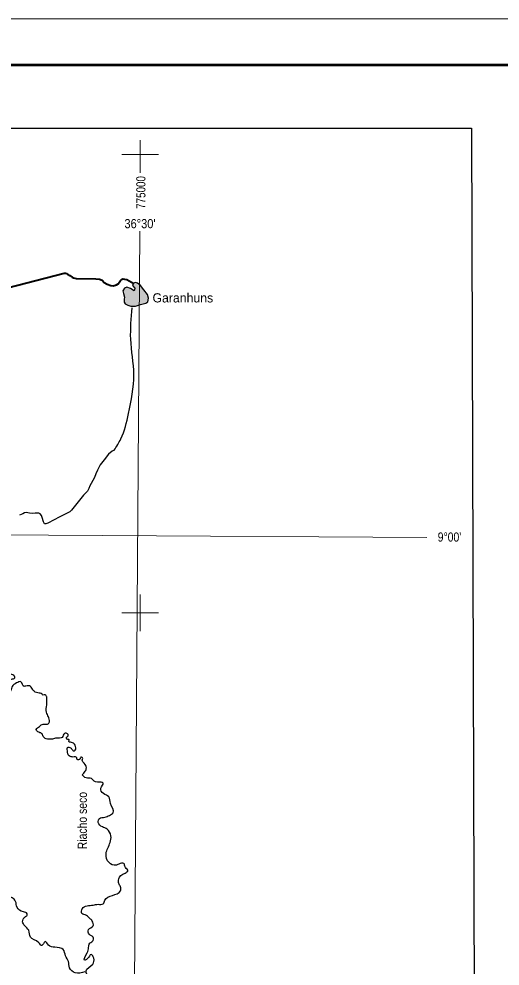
# Model space of a CAD drawing. Extents: x 553962 to 842807, y 8883888 to 9032388.
# Drawn here: x 768390 to 794627, y 8980740 to 9032388 of the extents above; entities that cross this region are included whole.
import ezdxf
from ezdxf.enums import TextEntityAlignment as Align

# ---------------------------------------------------------------- set-up
doc = ezdxf.new("R2010")
doc.units = 0
doc.header["$LTSCALE"] = 200
for name, color, linetype, lineweight in [('1', 7, 'Continuous', 13), ('12', 7, 'Continuous', 25), ('2', 7, 'Continuous', 13), ('21', 7, 'Continuous', 25), ('24', 7, 'Continuous', 25), ('3', 7, 'Continuous', 13)]:
    doc.layers.add(name, color=color, linetype=linetype, lineweight=lineweight)
for name, color, linetype in [('41', 7, 'Continuous'), ('46', 7, 'Continuous'), ('47', 7, 'Continuous'), ('49', 7, 'Continuous')]:
    doc.layers.add(name, color=color, linetype=linetype)

msp = doc.modelspace()

# ---------------------------------------------------------------- hatches: boundary and pattern name
at = {"layer": '21'}
msp.add_hatch(color=256, dxfattribs=at).paths.add_polyline_path([(774642.6, 9017970.5), (774590, 9017853.5), (774707, 9017703.1), (774699.9, 9017607.5), (774666.4, 9017564.6), (774465.8, 9017695.9), (774272.4, 9017755.6), (774141.1, 9017703.1), (774059.9, 9017559.8), (774088.6, 9017407), (774150.6, 9017220.7), (774131.5, 9017098.9), (774119.6, 9016950.8), (774174.5, 9016850.6), (774322.6, 9016774.1), (774496.9, 9016721.6), (774740.5, 9016728.8), (775024.6, 9016812.3), (775308.8, 9016886.4), (775418.6, 9016962.8), (775461.6, 9017165.8), (775401.9, 9017366.4), (775199, 9017617.1), (775010.3, 9017846.3), (774859.9, 9017984.8), (774742.8, 9018020.7)])

# ---------------------------------------------------------------- linework, layer by layer
at = {"layer": '1'}
for points in [[(774987.1, 9020818), (774482.3, 8948876), (774053.6, 8890875.3)], [(565303.2, 9005146.6), (664889.8, 9004806.7), (719872.1, 9004543.9), (790635.8, 9004109)]]:
    msp.add_lwpolyline(points, dxfattribs=at)
at = {"layer": '12', "lineweight": 40}
msp.add_lwpolyline([(756511.8, 9014822.1), (770853.3, 9018520.5), (770924.2, 9018521.6), (770985.1, 9018512.5), (771046.6, 9018462.9), (771159, 9018394), (771296.8, 9018315.3), (771363.3, 9018270.9), (771439.6, 9018246.8), (771515.7, 9018237.9), (772584.4, 9018214.5), (772792.2, 9018202.7), (772924.7, 9018144.2), (773037.8, 9018024.7), (773196.2, 9017926.1), (773399.7, 9017858.6), (773526.7, 9017830.3), (773718.2, 9017894), (773793.5, 9017940.7), (773853.2, 9018012.4), (773922.3, 9018129.7), (773982.4, 9018176.2), (774057.9, 9018207.7), (774154.2, 9018199.1), (774276, 9018180.9), (774647, 9017969.3)], dxfattribs=at)
at = {"layer": '12'}
msp.add_lwpolyline([(773619.5, 9008873.2), (773587.2, 9008870.6), (773476.6, 9008818.3), (773271.3, 9008663.4), (773032.9, 9008346.2), (772824.1, 9008080.1), (772676.6, 9007784.6), (772578.4, 9007575.8), (772510.4, 9007377.7), (772338, 9007051.5), (772258.8, 9006923.8), (772200.1, 9006786.5), (772121.2, 9006638.6), (772006.6, 9006510.5), (771906.7, 9006417.9), (771255.5, 9005598.9), (771165.5, 9005516.6), (770688.2, 9005266.4), (770582.6, 9005214.1), (770316.2, 9005078.5), (769969.7, 9004886), (769853.6, 9004863.9), (769792.8, 9004862.9), (769725.5, 9004968), (769651, 9005209.4), (769624.2, 9005310), (769552.1, 9005394.8), (769470.5, 9005439), (769278.1, 9005435.9), (769146.7, 9005418.7), (768969.3, 9005431), (768781.4, 9005468.4), (768690.5, 9005456.9), (768600, 9005409.9), (768419.6, 9005320.2)], dxfattribs=at)
msp.add_spline([(773587.2, 9008870.6), (773945.5, 9009485.9), (774363.7, 9010866.4), (774656.4, 9013000.1), (774489.1, 9014924.5), (774572.8, 9016639.8)], degree=3, dxfattribs=at)
at = {"layer": '2'}
for p, q in [((775000, 9024000), (775000, 9025783.6)), ((774000, 9025000), (776000, 9025000)), ((775000, 8999000), (775000, 9001000)), ((774000, 9000000), (776000, 9000000))]:
    msp.add_line(p, q, dxfattribs=at)
at = {"layer": '21'}
msp.add_lwpolyline([(774642.6, 9017970.5), (774590, 9017853.5), (774707, 9017703.1), (774699.9, 9017607.5), (774666.4, 9017564.6), (774465.8, 9017695.9), (774272.4, 9017755.6), (774141.1, 9017703.1), (774059.9, 9017559.8), (774088.6, 9017407), (774150.6, 9017220.7), (774131.5, 9017098.9), (774119.6, 9016950.8), (774174.5, 9016850.6), (774322.6, 9016774.1), (774496.9, 9016721.6), (774740.5, 9016728.8), (775024.6, 9016812.3), (775308.8, 9016886.4), (775418.6, 9016962.8), (775461.6, 9017165.8), (775401.9, 9017366.4), (775199, 9017617.1), (775010.3, 9017846.3), (774859.9, 9017984.8), (774742.8, 9018020.7)], close=True, dxfattribs=at)
at = {"layer": '24'}
for points in [[(771454.5, 8992786.6), (771363.4, 8992894.2), (771259, 8992936.7), (771154.7, 8992956), (771112.2, 8992994.7), (771127.6, 8993052.7), (771104.5, 8993091.4), (771004, 8993114.6), (770984.7, 8993219), (771054.2, 8993269.2), (771081.3, 8993323.4), (770961.5, 8993435.5), (770876.5, 8993423.9), (770745.1, 8993211.2), (770443.7, 8993172.6), (770227.3, 8993114.6), (770072.7, 8993110.7), (769817.6, 8993157.1), (769694, 8993307.9), (769655.3, 8993400.7), (769477.6, 8993485.8), (769338.5, 8993640.5), (769404.2, 8993733.3), (769520.1, 8993806.7), (769601.2, 8993895.7), (769833.1, 8993922.7), (770026.3, 8993980.7), (770053.4, 8994139.3), (770026.3, 8994270.7), (769918.1, 8994514.3), (769875.6, 8994672.9), (769914.3, 8995094.4), (769910.4, 8995237.4), (769910.4, 8995419.2), (769879.5, 8995477.2), (769829.2, 8995523.6), (769713.3, 8995519.7), (769655.3, 8995566.1), (769425.4, 8995635.7), (769162.7, 8995774.9), (769023.6, 8995991.4), (768760.8, 8996006.9), (768683.5, 8995991.4), (768498, 8996238.9), (768266.2, 8996177), (768018.8, 8995991.4), (767941.5, 8995759.4), (767740.6, 8995620.2), (767632.4, 8995697.6), (767323.3, 8995728.5), (767431.5, 8995945), (767663.3, 8996022.4), (767771.5, 8996238.9), (767987.9, 8996393.6), (768157.9, 8996455.5), (768142.5, 8996548.2), (767941.5, 8996656.5), (767833.3, 8996702.9), (767323.3, 8996409.1), (767014.1, 8996625.6), (766998.7, 8996981.3), (767091.4, 8997151.5), (766735.9, 8997136), (766148.5, 8997120.5), (766086.7, 8997429.9), (766210.3, 8997770.2), (766117.6, 8997924.8), (765932.1, 8997832), (765715.7, 8997940.3), (765823.9, 8998218.7), (765793, 8998435.2), (765793, 8998729.1), (765576.6, 8998837.4), (765375.7, 8998775.5), (765252, 8998992.1), (765329.3, 8999409.7), (765004.7, 8999517.9), (764772.8, 8999332.3), (764633.7, 8998976.6), (764278.2, 8998667.2), (764061.8, 8998760), (764200.9, 8999440.6), (764479.1, 8999657.1), (764602.8, 8999873.7), (764231.8, 9000059.3), (763690.8, 9000616.1), (763752.6, 9000832.6), (763969, 9001018.2), (764200.9, 9001126.5), (764355.5, 9001528.7), (764711, 9001606)], [(771983.6, 8980431.6), (771458.1, 8980369.7), (771148.9, 8980648.1), (771087.1, 8980988.4), (770932.5, 8981297.7), (770808.9, 8981638), (770345.2, 8981761.8), (770005.1, 8981885.5), (769819.6, 8982071.1), (769634.1, 8981854.6), (769479.5, 8982009.2), (769015.8, 8982318.6), (768923.1, 8982689.8), (768706.7, 8982937.2), (768593.5, 8983157.4), (768713.2, 8983415.3), (768842, 8983516.6), (768842, 8983590.2), (768630.3, 8983700.8), (768289.8, 8983940.2), (768207, 8984262.5), (768022.9, 8984465.2), (767700.8, 8984557.2), (767590.3, 8984640.1), (767553.5, 8985036.1), (767599.5, 8985266.4), (767599.5, 8985422.9), (767461.5, 8985607.1), (767314.2, 8985634.8), (767268.2, 8985533.4), (767139.4, 8985496.6), (766918.5, 8985616.3), (766789.6, 8985818.9), (766559.5, 8985957.1), (766219, 8986297.8), (765850.9, 8986500.4), (765363.1, 8986924.1), (764801.7, 8987504.3), (764663.6, 8987624), (764378.3, 8988066), (764295.5, 8988259.4), (764221.8, 8988296.3), (764083.8, 8988204.2), (763982.5, 8988268.6), (763669.6, 8988664.7), (763586.8, 8988683.1), (763540.8, 8988848.8), (763605.2, 8988913.3), (763665, 8988922.5), (763720.2, 8989088.3), (763554.6, 8989254.1), (763480.9, 8989475.1), (763628.2, 8989677.7), (763977.9, 8989935.6), (764143.6, 8990101.3), (764125.2, 8990285.5), (763849.1, 8990377.6), (763793.9, 8990525), (763591.4, 8990617.1), (763480.9, 8990635.5), (763260.1, 8990525), (763094.4, 8990525), (762965.5, 8990635.5), (762818.3, 8990856.5), (762781.5, 8990930.2), (762652.6, 8990967), (762450.1, 8991169.6), (762082, 8991335.4), (761916.3, 8991464.3), (761750.7, 8991464.3), (761640.2, 8991261.7), (761456.2, 8991059.1), (761382.5, 8990967), (761290.5, 8990948.6), (761198.5, 8991059.1), (761143.2, 8991298.6), (760867.1, 8991464.3), (760738.3, 8991666.9), (760499, 8991795.9), (760351.7, 8992035.3), (760094, 8992495.8), (759854.7, 8992403.7), (759652.3, 8992256.3), (759394.6, 8992477.3), (758971.2, 8992643.1), (758731.9, 8992753.6), (758639.9, 8993048.3), (758566.2, 8993324.6), (758695.1, 8993508.8), (758916, 8993453.6), (758879.2, 8993619.3)], [(771844.7, 8991166.7), (772006.9, 8991369.5), (772067.7, 8991552), (771954.6, 8991796), (771846.4, 8991966.2), (771873.5, 8992066.7), (771842.5, 8992113.1), (771769.1, 8992132.4), (771715, 8992043.5), (771645.5, 8991985.5), (771564.3, 8992012.6), (771545, 8992101.5), (771351.8, 8992140.2), (771235.8, 8992151.8), (771050.3, 8992314.2), (771034.9, 8992480.4), (771023.3, 8992604.2), (771077.4, 8992677.6), (771162.4, 8992654.4), (771232, 8992615.8), (771332.5, 8992499.8), (771382.7, 8992476.6), (771456.1, 8992507.5), (771498.6, 8992646.7), (771452.2, 8992793.6)], [(774675.9, 8971457.7), (774621.3, 8971839.9), (774398.4, 8971961.6), (774175.5, 8972002.1), (774175.5, 8972387.4), (774317.3, 8972793), (774398.4, 8972955.3), (774297.1, 8973158.1), (773891.7, 8973300), (773810.7, 8973421.7), (773506.6, 8973847.6), (773222.9, 8973888.2), (773182.4, 8974151.8), (773222.9, 8974314), (773466.1, 8974334.3), (773648.5, 8974557.4), (773871.5, 8974618.2), (774094.4, 8974435.7), (774317.3, 8974598), (774540.3, 8974902.2), (774722.7, 8975105), (774580.8, 8975226.6), (774175.5, 8975186.1), (773749.8, 8975429.4), (773668.8, 8975936.4), (773385, 8976402.9), (773324.2, 8976930.1), (773486.4, 8977538.5), (773810.7, 8978248.3), (773810.7, 8978430.9), (773466.1, 8978430.9), (773182.4, 8978491.7), (772918.9, 8979100.1), (772817.6, 8979221.8), (772371.7, 8979465.1), (772189.3, 8980093.8), (772047.4, 8980479.1), (772412.2, 8980844.2), (772473, 8981168.7), (772331.2, 8981371.5), (772108.2, 8981128.1), (771966.3, 8981067.3), (772108.2, 8981452.6), (772189.3, 8981756.8), (772250.1, 8981979.9), (772392, 8982081.3), (772432.5, 8982324.6), (772229.8, 8982466.6), (772189.3, 8982730.2), (772432.5, 8982933), (772392, 8983196.7), (772250.1, 8983338.6), (772067.7, 8983500.8), (771824.5, 8983602.2), (771844.8, 8983865.9), (772432.5, 8984068.7), (772716.2, 8984109.2), (772979.7, 8984129.5), (773081, 8984332.3), (773486.4, 8984596), (773932.3, 8984839.3), (773932.3, 8985062.4), (773830.9, 8985244.9), (773830.9, 8985488.3), (774175.5, 8985812.8), (774337.6, 8985934.5), (774195.7, 8986117), (774114.7, 8986340.1), (773830.9, 8986299.5), (773668.8, 8986238.7), (773304, 8986380.6), (773141.8, 8986867.3), (773364.8, 8987475.7), (773405.3, 8987840.8), (773202.6, 8988205.8), (772939.2, 8988327.5), (772716.2, 8988570.8), (772777, 8988793.9), (773081, 8988854.8), (773324.2, 8988956.2), (773526.9, 8989098.1), (773385, 8989605.1), (773283.7, 8989970.2), (773000, 8990152.7), (772858.1, 8990436.6), (772979.7, 8990720.5), (772878.4, 8990761.1), (772493.3, 8990821.9), (772351.4, 8990963.9), (772047.4, 8991004.4), (771844.7, 8991166.7)]]:
    msp.add_spline(points, degree=3, dxfattribs=at)
at = {"layer": '3'}
msp.add_lwpolyline([(842807.3, 9032387.8), (842807.3, 8883887.8), (553961.7, 8883887.8), (553961.7, 9032387.8)], close=True, dxfattribs=at)
msp.add_lwpolyline([(842807.3, 9032387.8), (842807.3, 8883887.8), (553961.7, 8883887.8), (553961.7, 9032387.8)], close=True, dxfattribs=at)
at = {"layer": '3', "lineweight": 53}
msp.add_lwpolyline([(840307.3, 9029887.8), (840307.3, 8886387.8), (560211.7, 8886387.8), (560211.7, 9029887.8)], close=True, dxfattribs=at)
msp.add_lwpolyline([(840307.3, 9029887.8), (840307.3, 8886387.8), (560211.7, 8886387.8), (560211.7, 9029887.8)], close=True, dxfattribs=at)
at = {"layer": '3', "lineweight": 25}
msp.add_lwpolyline([(563033.9, 9026438.8), (793061.1, 9026438.8), (793495.6, 8889836.8), (563468.3, 8889836.8)], close=True, dxfattribs=at)
msp.add_lwpolyline([(563033.9, 9026438.8), (793061.1, 9026438.8), (793495.6, 8889836.8), (563468.3, 8889836.8)], close=True, dxfattribs=at)

# ---------------------------------------------------------------- texts
at = {"layer": '41'}
msp.add_text('Garanhuns', height=500, dxfattribs=at).set_placement((775675, 9016928.7))
at = {"layer": '46'}
for s, width, p in [("36°30'", 0.9, (774990.8, 9020976.4)), ("9°00'", 0.85, (791868.9, 9003886.2))]:
    msp.add_text(s, height=500, dxfattribs=dict(at, width=width)).set_placement(p, align=Align.CENTER)
at = {"layer": '47', "width": 0.8}
msp.add_text('775000', height=500, rotation=90, dxfattribs=at).set_placement((775287.3, 9022925.4), align=Align.CENTER)
at = {"layer": '49', "width": 0.85}
msp.add_text('Riacho seco', height=500, rotation=90, dxfattribs=at).set_placement((772094.2, 8988672), align=Align.CENTER)

doc.saveas('drawing.dxf')
